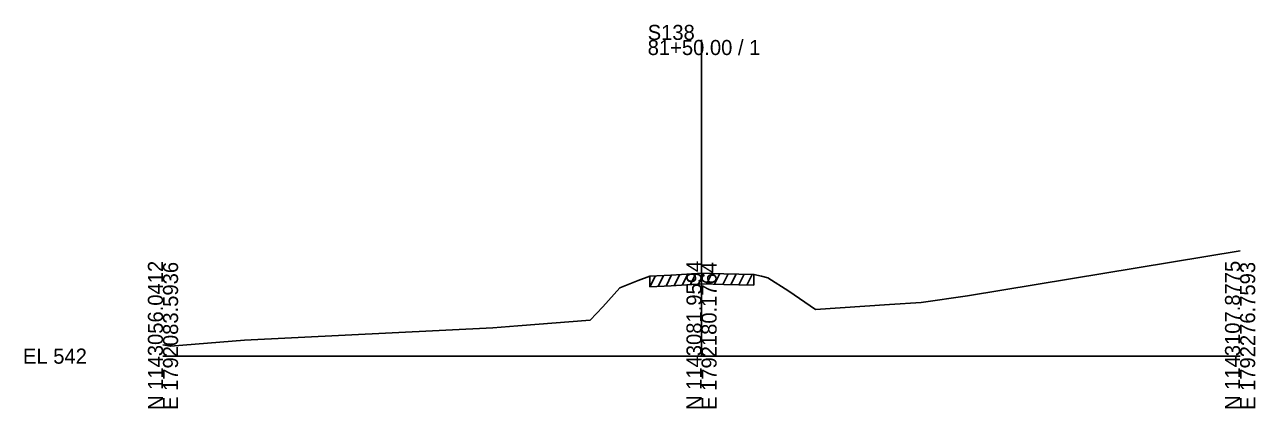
# Model space of a CAD drawing. Extents: x -26 to 1203, y -10 to 19606.
# Drawn here: x -25.7 to 202.8, y 2990.3 to 3061.5 of the extents above; entities that cross this region are included whole.
import ezdxf

# ---------------------------------------------------------------- set-up
doc = ezdxf.new("R2010")
doc.units = 0
for name, color, linetype in [('RD_EX_Driveway', 7, 'Continuous'), ('RD_GPK_XS_Cell', 7, 'Continuous'), ('RD_XS_ExGround', 7, 'Continuous'), ('RD_XS_ExPaveRet', 7, 'Continuous')]:
    doc.layers.add(name, color=color, linetype=linetype)

msp = doc.modelspace()

# ---------------------------------------------------------------- linework, layer by layer
at = {"layer": 'RD_GPK_XS_Cell'}
for p, q in [((100, 3000), (100, 3058.68)), ((0, 3000), (100, 3000)), ((100, 3000), (200, 3000))]:
    msp.add_line(p, q, dxfattribs=at)
at = {"layer": 'RD_XS_ExGround'}
msp.add_lwpolyline([(0, 3002.1), (1.39, 3001.84), (15.14, 3002.95), (61.25, 3005.23), (65.92, 3005.61), (79.3, 3006.67), (81.7, 3009.17), (84.82, 3012.65), (88.23, 3014.01), (90.43, 3014.85), (94.36, 3015.05), (100.14, 3015.4), (104.15, 3015.3), (109.73, 3015.17), (111.14, 3014.83), (112.32, 3014.51), (116.19, 3012.04), (121.19, 3008.68), (134.9, 3009.58), (140.81, 3009.97), (149.38, 3011.18), (200, 3019.56)], dxfattribs=at)
at = {"layer": 'RD_XS_ExPaveRet'}
for p, q in [((90.43, 3012.85), (91.45, 3014.9)), ((90.43, 3012.85), (90.43, 3014.85)), ((91.93, 3012.93), (92.95, 3014.98)), ((93.43, 3013), (94.45, 3015.06)), ((94.93, 3013.09), (95.96, 3015.15)), ((96.43, 3013.18), (97.46, 3015.24)), ((97.93, 3013.27), (98.96, 3015.33)), ((99.43, 3013.36), (100.44, 3015.39)), ((100.93, 3013.38), (101.91, 3015.35)), ((102.43, 3013.34), (103.41, 3015.31)), ((103.93, 3013.3), (104.92, 3015.28)), ((105.43, 3013.27), (106.42, 3015.24)), ((106.93, 3013.23), (107.92, 3015.21)), ((108.43, 3013.2), (109.42, 3015.17)), ((109.73, 3015.17), (109.73, 3013.17)), ((90.43, 3012.85), (94.36, 3013.05)), ((94.36, 3013.05), (100.14, 3013.4)), ((100.14, 3013.4), (104.15, 3013.3)), ((104.15, 3013.3), (109.73, 3013.17))]:
    msp.add_line(p, q, dxfattribs=at)

# ---------------------------------------------------------------- texts
at = {"layer": 'RD_EX_Driveway'}
msp.add_text('549.70', height=0.0975, rotation=90, dxfattribs=at).set_placement((100.1, 3015.39))
at = {"layer": 'RD_GPK_XS_Cell'}
for s, p in [('S138', (90, 3058.68)), ('81+50.00 / 1', (90, 3055.88)), ('EL 542', (-26, 2998.6))]:
    msp.add_text(s, height=2.8, dxfattribs=at).set_placement(p)
for s, p in [('N 1143056.0412', (0, 2990)), ('E 1792083.5936', (2.8, 2990)), ('N 1143081.9594', (100, 2990)), ('E 1792180.1764', (102.8, 2990)), ('N 1143107.8775', (200, 2990)), ('E 1792276.7593', (202.8, 2990))]:
    msp.add_text(s, height=2.8, rotation=90, dxfattribs=at).set_placement(p)

doc.saveas('drawing.dxf')
